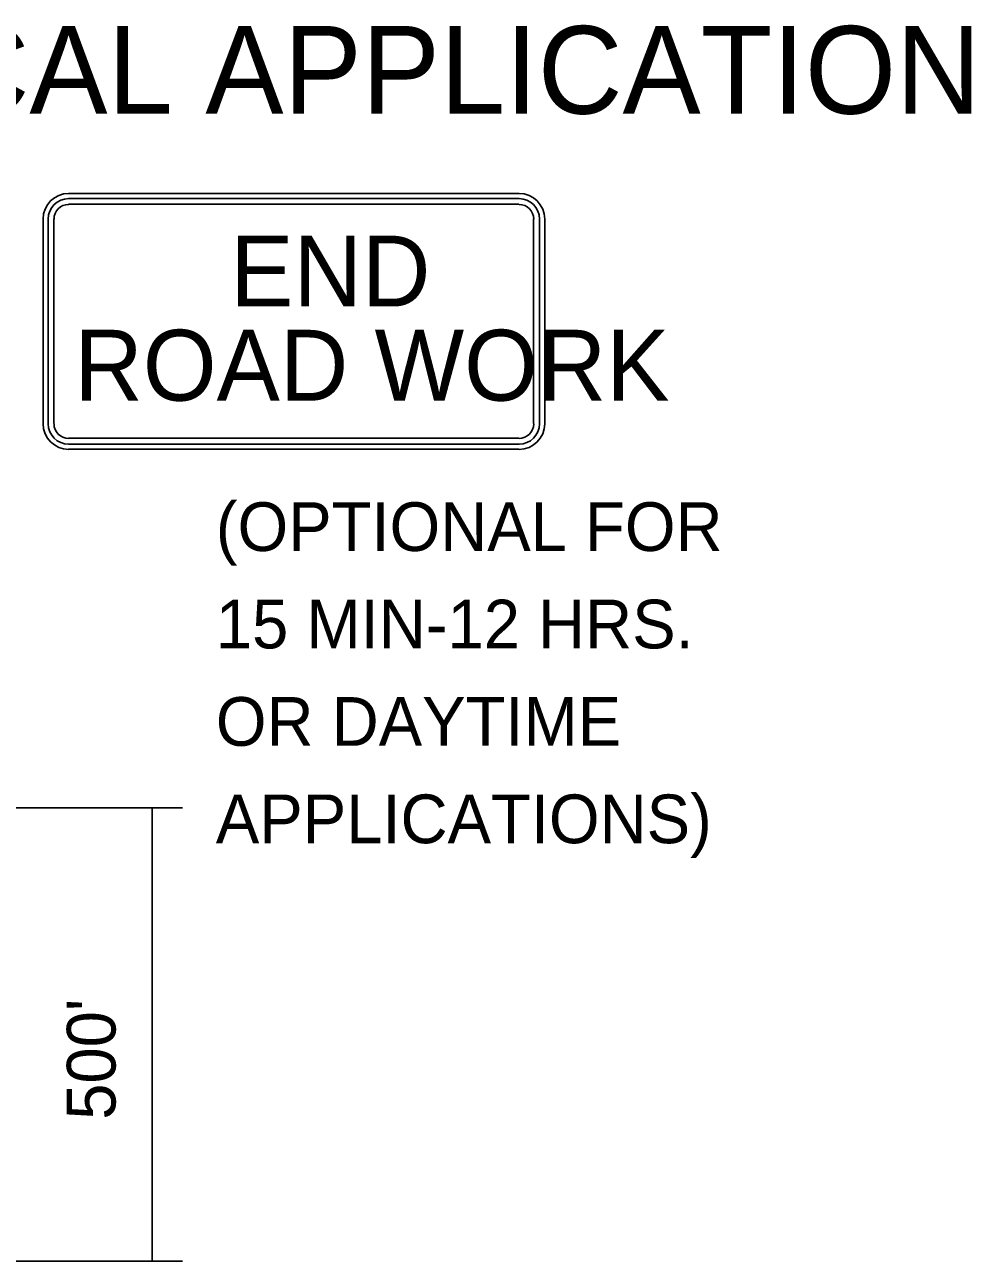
# Model space of a CAD drawing. Extents: x 1531.3 to 1538.6, y 1529.6 to 1539.7.
# Drawn here: x 1535.513 to 1536.679, y 1538.182 to 1539.705 of the extents above; entities that cross this region are included whole.
import ezdxf

# ---------------------------------------------------------------- set-up
doc = ezdxf.new("R2010")
doc.units = 0
for name, color, linetype in [('DETL-DIMS', 7, 'Continuous'), ('DETL-LINE', 7, 'Continuous'), ('DETL-NOTE', 7, 'Continuous'), ('DETL-TITL', 7, 'Continuous')]:
    doc.layers.add(name, color=color, linetype=linetype)

msp = doc.modelspace()

# ---------------------------------------------------------------- linework, layer by layer
at = {"layer": 'DETL-DIMS'}
for p, q in [((1535.335, 1538.7404), (1535.7074, 1538.7404)), ((1535.67, 1538.7404), (1535.67, 1538.1817)), ((1535.2044, 1538.1817), (1535.7074, 1538.1817))]:
    msp.add_line(p, q, dxfattribs=at)
at = {"layer": 'DETL-LINE'}
for p, q in [((1536.1216, 1539.4972), (1535.5669, 1539.4972)), ((1535.5669, 1539.4908), (1536.1216, 1539.4908)), ((1535.5669, 1539.4841), (1536.1216, 1539.4841)), ((1535.5356, 1539.4658), (1535.5356, 1539.2136)), ((1535.542, 1539.2136), (1535.542, 1539.4658)), ((1535.5486, 1539.2136), (1535.5486, 1539.4658)), ((1536.1396, 1539.4658), (1536.1396, 1539.2136)), ((1536.1397, 1539.4656), (1536.1396, 1539.4658)), ((1536.1469, 1539.4658), (1536.1469, 1539.2136)), ((1536.1533, 1539.2136), (1536.1533, 1539.4658)), ((1536.1216, 1539.1956), (1535.5669, 1539.1956)), ((1536.1216, 1539.1884), (1535.5669, 1539.1884)), ((1535.5669, 1539.182), (1536.1216, 1539.182))]:
    msp.add_line(p, q, dxfattribs=at)
for centre, radius, start, end in [((1535.5671, 1539.4656), 0.0316, 90, 180), ((1535.5671, 1539.4656), 0.0252, 90, 180), ((1536.1217, 1539.4656), 0.0316, 0, 90), ((1536.1217, 1539.4656), 0.0252, 0, 90), ((1535.5671, 1539.4656), 0.0181, 90, 180), ((1536.1217, 1539.4656), 0.0181, 0, 90), ((1535.5671, 1539.2135), 0.0316, 180, 270), ((1535.5671, 1539.2135), 0.0252, 180, 270), ((1535.5671, 1539.2135), 0.0181, 180, 270), ((1536.1217, 1539.2135), 0.0316, 270, 0), ((1536.1217, 1539.2135), 0.0181, 270, 0), ((1536.1217, 1539.2135), 0.0252, 270, 0)]:
    msp.add_arc(centre, radius, start, end, dxfattribs=at)

# ---------------------------------------------------------------- texts
for s, p in [('END', (1535.7661, 1539.3579)), ('ROAD WORK', (1535.5741, 1539.2419))]:
    msp.add_text(s, height=0.08731, rotation=360, dxfattribs=at).set_placement(p)
at = {"layer": 'DETL-NOTE'}
for s, p in [('(OPTIONAL FOR', (1535.7483, 1539.0567)), ('15 MIN-12 HRS. ', (1535.7483, 1538.9367)), ('OR DAYTIME', (1535.7483, 1538.8167)), ('APPLICATIONS)', (1535.7483, 1538.6967))]:
    msp.add_text(s, height=0.06, dxfattribs=at).set_placement(p)
msp.add_text("500'", height=0.06, rotation=90, dxfattribs=at).set_placement((1535.6248, 1538.356))
at = {"layer": 'DETL-TITL'}
msp.add_text('TEMPORARY TRAFFIC CONTROL TYPICAL APPLICATION', height=0.108, dxfattribs=at).set_placement((1532.7424, 1539.5954))

doc.saveas('drawing.dxf')
